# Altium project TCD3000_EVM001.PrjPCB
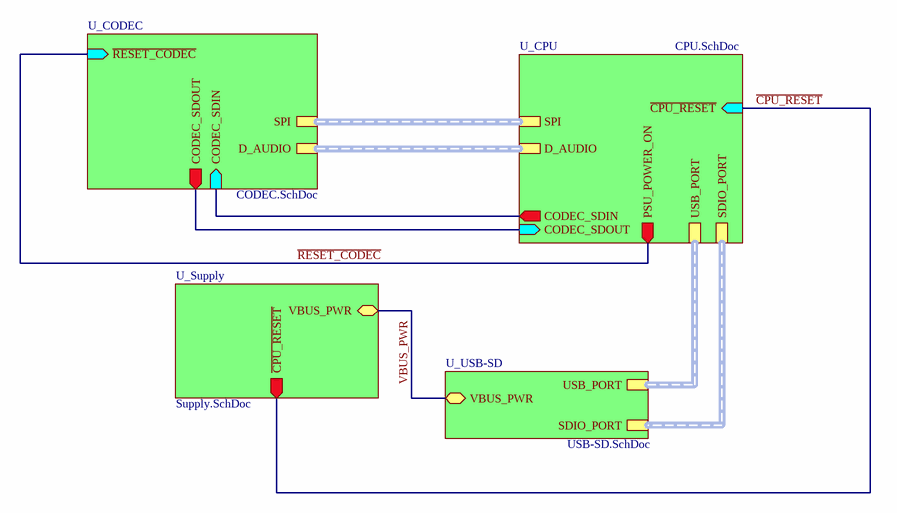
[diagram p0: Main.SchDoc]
6 sheets, 201 parts. Net scope: hierarchical (ports join the sheet entries above them; power ports are global).
Sheets:
  Main.SchDoc
    U_CPU = CPU.SchDoc
      U_CPU_Supply = CPU_Supply.SchDoc
    U_USB-SD = USB-SD.SchDoc
    U_CODEC = CODEC.SchDoc
    U_Supply = Supply.SchDoc

## Sheet Main.SchDoc: TCD3000-EVM001 REV2.0
size A4; Organization: TC Applied Technologies; Address4: address 4; DocumentNumber: 1; Revision: F; SheetNumber: 1; SheetTotal: 6

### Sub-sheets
U_CODEC = CODEC.SchDoc: SPI (harness SPI), D_AUDIO (harness D_AUDIO), CODEC_SDIN (in), CODEC_SDOUT (out), ~{RESET_CODEC} (in)
U_CPU = CPU.SchDoc: SDIO_PORT (harness SDIO), USB_PORT (harness USB), SPI (harness SPI), ~{CPU_RESET} (in), D_AUDIO (harness D_AUDIO), CODEC_SDIN (out), CODEC_SDOUT (in), PSU_POWER_ON (out)
U_Supply = Supply.SchDoc: ~{CPU_RESET} (out), VBUS_PWR
U_USB-SD = USB-SD.SchDoc: USB_PORT (harness USB), SDIO_PORT (harness SDIO), VBUS_PWR

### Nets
~{CPU_RESET}: sheet U_CPU/~{CPU_RESET}, sheet U_Supply/~{CPU_RESET}
CODEC_SDIN: sheet U_CPU/CODEC_SDIN, sheet U_CODEC/CODEC_SDIN
CODEC_SDOUT: sheet U_CPU/CODEC_SDOUT, sheet U_CODEC/CODEC_SDOUT
~{RESET_CODEC}: sheet U_CPU/PSU_POWER_ON, sheet U_CODEC/~{RESET_CODEC}  [project net PSU_POWER_ON]
VBUS_PWR: sheet U_USB-SD/VBUS_PWR, sheet U_Supply/VBUS_PWR

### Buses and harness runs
harness sheet U_CODEC/D_AUDIO = sheet U_CPU/D_AUDIO
harness sheet U_CODEC/SPI = sheet U_CPU/SPI
harness sheet U_CPU/SDIO_PORT = sheet U_USB-SD/SDIO_PORT
harness sheet U_CPU/USB_PORT = sheet U_USB-SD/USB_PORT

## Sheet CPU.SchDoc: TCD3000-EVM001 REV2.0
size A3; Organization: TC Applied Technologies; DocumentNumber: 1; Revision: F; SheetNumber: 4; SheetTotal: 6
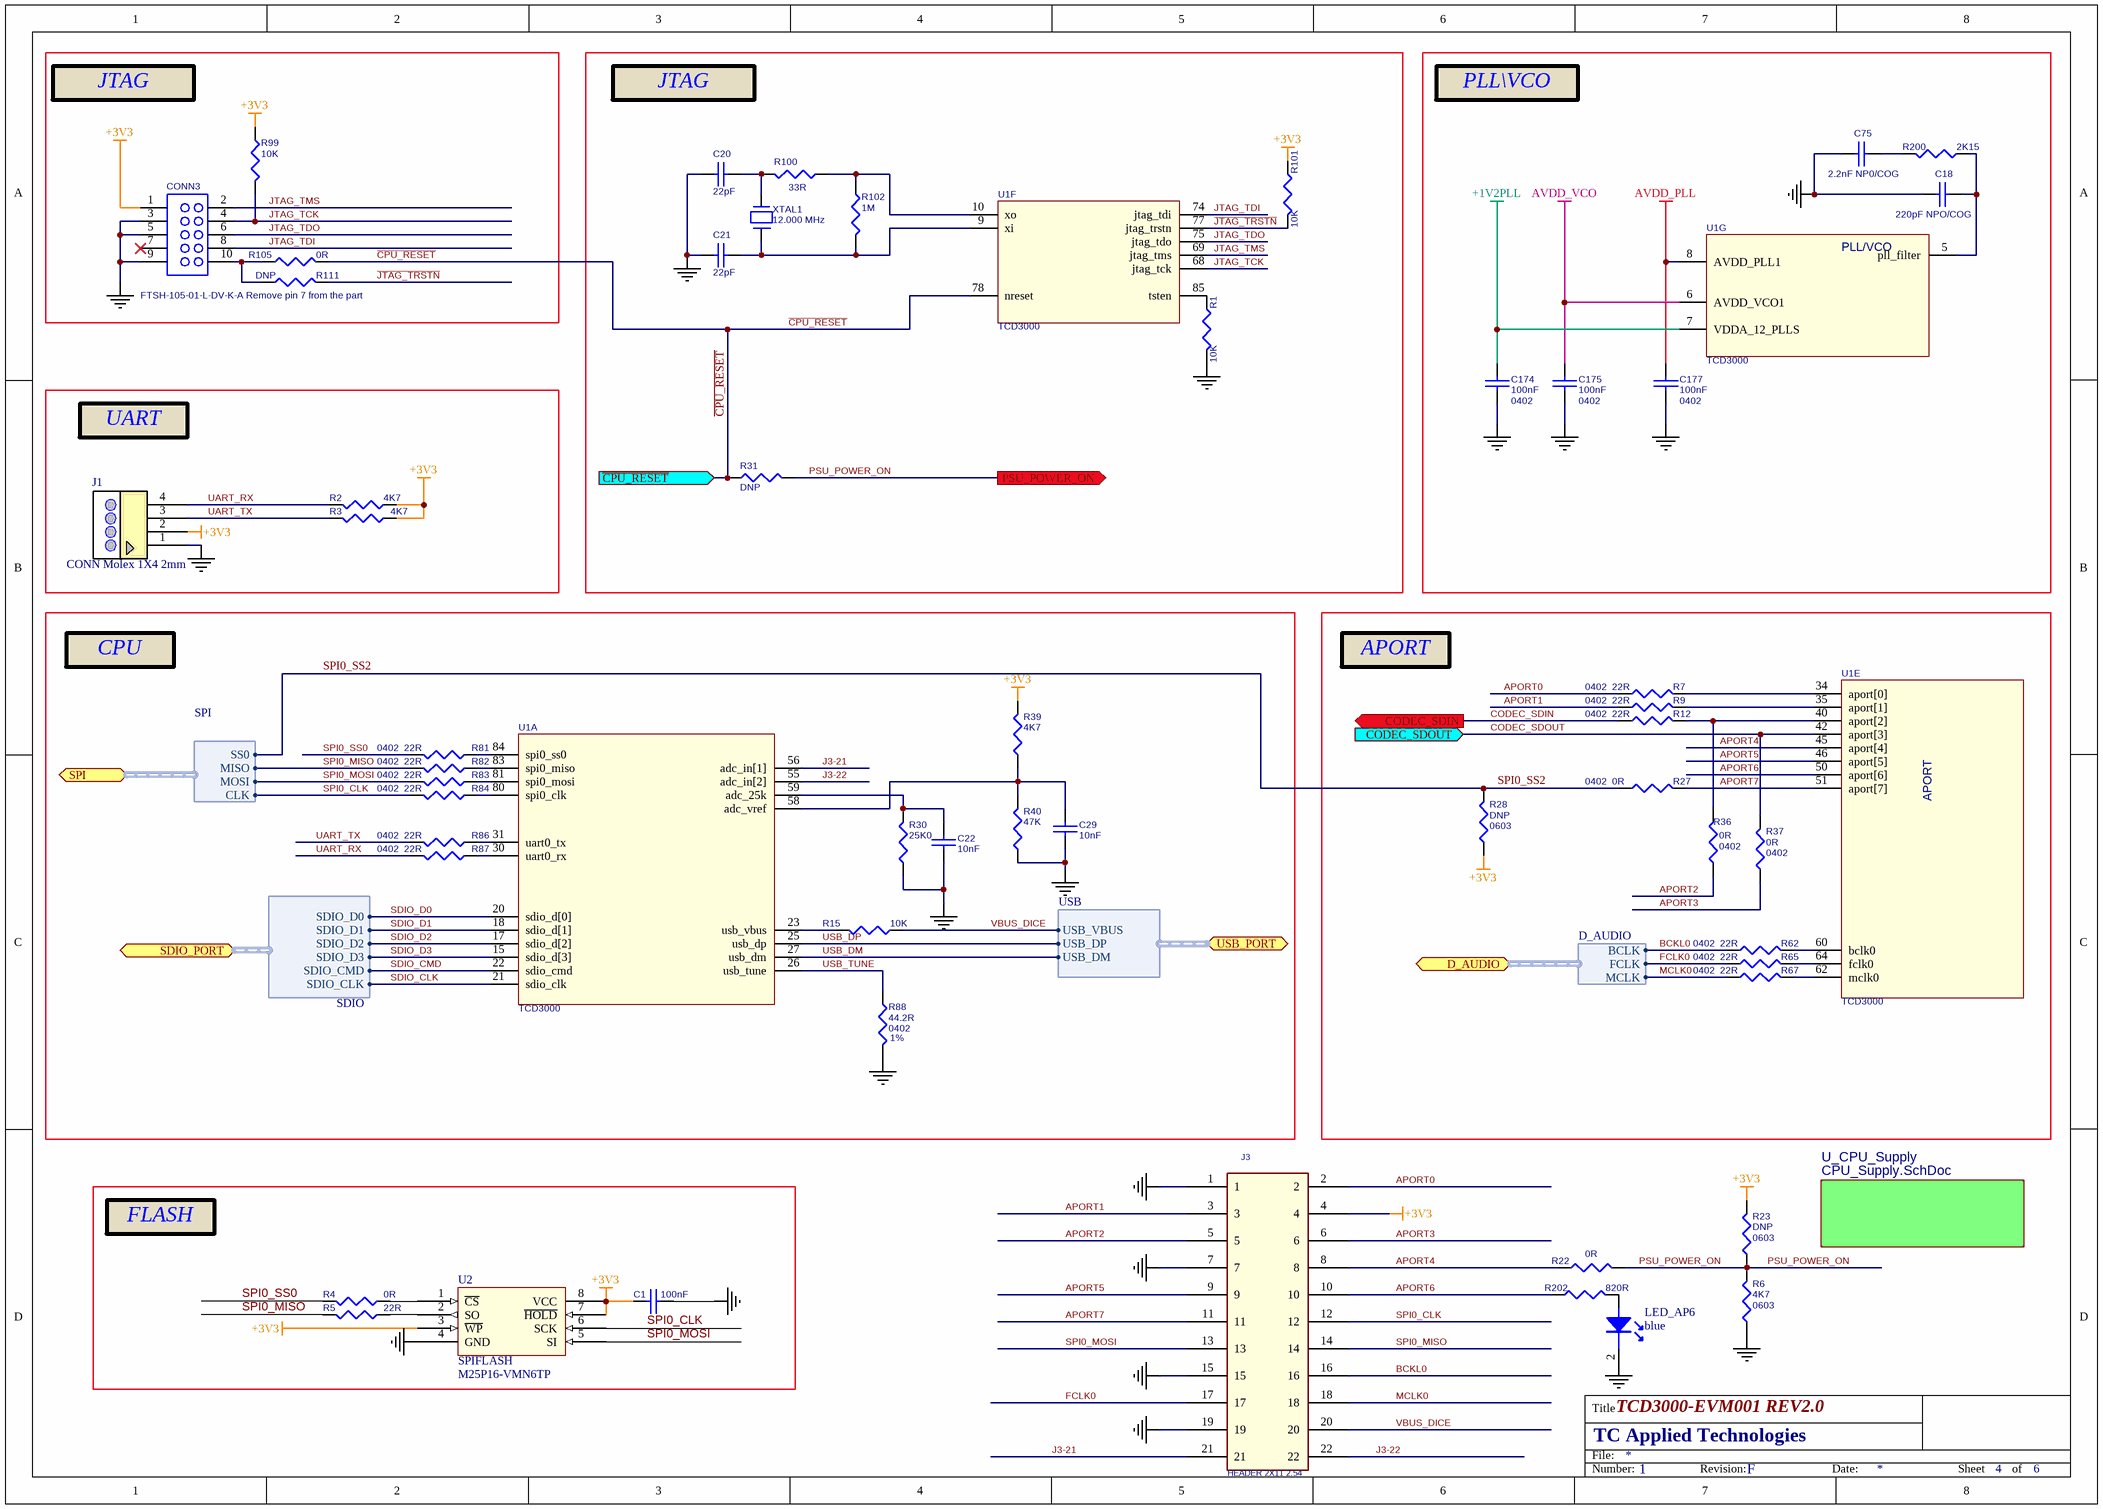
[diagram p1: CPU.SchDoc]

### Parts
C1  100nF  [0402_C]
C18  220pF NPO/COG  [0603_c]
C20  22pF  [0603_c]
C21  22pF  [0603_c]
C22  10nF  [0402_C]
C29  10nF  [0402_C]
C75  2.2nF NP0/COG  [0603_c]
C174  100nF  CASE: 0402  [0402_C]
C175  100nF  CASE: 0402  [0402_C]
C177  100nF  CASE: 0402  [0402_C]
CONN3  FTSH-105-01-L-DV-K-A Remove pin 7 from the part  [FTSH-105-01-L-DV-K-A]
J1  CONN Molex 1X4 2mm  [MOLEX 4POS 2MM VERT]
J3  HEADER 2X11 2.54  [CON/2X11/.100]
LED_AP6  blue  [LED_1 0805]
R1  10K  [0603_R]
R2  4K7  [0603_R]
R3  4K7  [0603_R]
R4  0R  [0402_R]
R5  22R  [0603_R]
R6  4K7  CASE: 0603  [0603_R]
R7  22R  CASE: 0402  [0402_R]
R9  22R  CASE: 0402  [0402_R]
R12  22R  CASE: 0402  [0402_R]
R15  10K  [0603_R]
R22  0R  [0402_R]
R23  DNP  CASE: 0603  [0603_R]
R27  0R  CASE: 0402  [0402_R]
R28  DNP  CASE: 0603  [0603_R]
R30  25K0  [0603_R]
R31  DNP  [0603_R]
R36  0R  CASE: 0402  [0402_R]
R37  0R  CASE: 0402  [0402_R]
R39  4K7  [0402_R]
R40  47K  [0402_R]
R62  22R  CASE: 0402  [0402_R]
R65  22R  CASE: 0402  [0402_R]
R67  22R  CASE: 0402  [0402_R]
R81  22R  CASE: 0402  [0402_R]
R82  22R  CASE: 0402  [0402_R]
R83  22R  CASE: 0402  [0402_R]
R84  22R  CASE: 0402  [0402_R]
R86  22R  CASE: 0402  [0402_R]
R87  22R  CASE: 0402  [0402_R]
R88  44.2R  CASE: 0402  TOLL: 1%  [0402_R]
R99  10K  [0603_R]
R100  33R  [0603_R]
R101  10K  [0603_R]
R102  1M  [0603_R]
R105  0R  [0402_R]
R111  DNP  [0603_R]
R200  2K15  [0603_R]
R202  820R  [0603_R]
U1  TCD3000  [QFN40P1000X1000X90-88USR]  (parts A,E,F,G of 7)
U2  SPIFLASH  Manufacturer Code: M25P16-VMN6TP  [SOIC150-8N]
XTAL1  12.000 MHz  [TXC 7A SERIES]

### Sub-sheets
U_CPU_Supply = CPU_Supply.SchDoc: no entries

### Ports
CODEC_SDIN (out), CODEC_SDOUT (in), D_AUDIO (harness D_AUDIO), PSU_POWER_ON (out), SDIO_PORT (harness SDIO), SPI (harness SPI), USB_PORT (harness USB), ~{CPU_RESET} (in)

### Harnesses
SDIO: SDIO_D1, SDIO_D2, SDIO_D3, SDIO_CMD, SDIO_CLK, SDIO_D0
USB: USB_VBUS, USB_DP, USB_DM
SPI: CLK, MISO, MOSI, SS0
D_AUDIO: BCLK, FCLK, MCLK

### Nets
+1V2PLL: C174.1 U1.7(VDDA_12_PLLS)
+3V3: C1.1 CONN3.1 J1.2 J3.4 R2.1 R3.1 R23.1 R28.2 R39.2 R99.2 R101.2 U2.3(~{WP}) U2.7(~{HOLD}) U2.8(VCC)
AVDD_PLL: C177.1 U1.8(AVDD_PLL1)
AVDD_VCO: C175.1 U1.6(AVDD_VCO1)
DGND: C1.2 C18.1 C20.2 C21.2 C22.1 C29.1 C75.1 C174.2 C175.2 C177.2 CONN3.3 CONN3.5 CONN3.9 J1.1 J3.1 J3.7 J3.15 J3.19 LED_AP6.2 R1.1 R6.2 R30.1 R40.1 R88.2 U2.4(GND)
APORT0: J3.2 R7.2
APORT1: J3.3 R9.2
APORT2: J3.5 R36.2
APORT3: J3.6 R37.2
APORT4: J3.8 R22.1 U1.45(aport[4])
APORT5: J3.9 U1.46(aport[5])
APORT6: J3.10 R202.1 U1.50(aport[6])
APORT7: J3.11 R27.1 U1.51(aport[7])
BCKL0: J3.16 R62.2 ; port D_AUDIO.BCLK
~{CPU_RESET}: R31.2 R105.1 U1.78(nreset) ; port ~{CPU_RESET}
CODEC_SDIN: R12.2 ; port CODEC_SDIN
CODEC_SDOUT: R37.1 U1.42(aport[3]) ; port CODEC_SDOUT
FCLK0: J3.17 R65.2 ; port D_AUDIO.FCLK
J3-21: J3.21 U1.56(adc_in[1])
J3-22: J3.22 U1.55(adc_in[2])
~{JTAG_TRSTN}: R101.1 R111.1 U1.77(jtag_trstn)
JTAG_TCK: CONN3.4 R99.1 U1.68(jtag_tck)
JTAG_TDI: CONN3.8 U1.74(jtag_tdi)
JTAG_TDO: CONN3.6 U1.75(jtag_tdo)
JTAG_TMS: CONN3.2 U1.69(jtag_tms)
MCLK0: J3.18 R67.2 ; port D_AUDIO.MCLK  [project net MCLK]
PSU_POWER_ON: R6.1 R22.2 R23.2 R31.1 ; port PSU_POWER_ON
SDIO_CLK: U1.21(sdio_clk) ; port SDIO_PORT.SDIO_CLK
SDIO_CMD: U1.22(sdio_cmd) ; port SDIO_PORT.SDIO_CMD
SDIO_D0: U1.20(sdio_d[0]) ; port SDIO_PORT.SDIO_D0
SDIO_D1: U1.18(sdio_d[1]) ; port SDIO_PORT.SDIO_D1
SDIO_D2: U1.17(sdio_d[2]) ; port SDIO_PORT.SDIO_D2
SDIO_D3: U1.15(sdio_d[3]) ; port SDIO_PORT.SDIO_D3
SPI0_CLK: J3.12 R84.2 U2.6(SCK) ; port SPI.CLK
SPI0_MISO: J3.14 R5.2 R82.2 ; port SPI.MISO
SPI0_MOSI: J3.13 R83.2 U2.5(SI) ; port SPI.MOSI
SPI0_SS0: R4.2 R81.2
SPI0_SS2: R27.2 R28.1 ; port SPI.SS0
UART_RX: J1.4 R2.2 R87.2
UART_TX: J1.3 R3.2 R86.2
USB_DM: U1.27(usb_dm) ; port USB_PORT.USB_DM  [project net HS_USB_N]
USB_DP: U1.25(usb_dp) ; port USB_PORT.USB_DP  [project net HS_USB_P]
USB_TUNE: R88.1 U1.26(usb_tune)
VBUS_DICE: J3.20 R15.2 ; port USB_PORT.USB_VBUS
NetC18_2: C18.2 R200.2 U1.5(pll_filter)
NetC20_1: C20.1 R100.2 XTAL1.1
NetC21_1: C21.1 R102.2 U1.9(xi) XTAL1.2
NetC22_2: C22.2 R30.2 U1.59(adc_25k)
NetC29_2: C29.2 R39.1 R40.2 U1.58(adc_vref)
NetC75_2: C75.2 R200.1
NetCONN3_10: CONN3.10 R105.2 R111.2
NetLED_AP6_1: LED_AP6.1 R202.2
NetR1_2: R1.2 U1.85(tsten)
NetR4_1: R4.1 U2.1(~{CS})
NetR5_1: R5.1 U2.2(SO)
NetR7_1: R7.1 U1.34(aport[0])
NetR9_1: R9.1 U1.35(aport[1])
NetR12_1: R12.1 R36.1 U1.40(aport[2])
NetR15_1: R15.1 U1.23(usb_vbus)
NetR62_1: R62.1 U1.60(bclk0)
NetR65_1: R65.1 U1.64(fclk0)
NetR67_1: R67.1 U1.62(mclk0)
NetR81_1: R81.1 U1.84(spi0_ss0)
NetR82_1: R82.1 U1.83(spi0_miso)
NetR83_1: R83.1 U1.81(spi0_mosi)
NetR84_1: R84.1 U1.80(spi0_clk)
NetR86_1: R86.1 U1.31(uart0_tx)
NetR87_1: R87.1 U1.30(uart0_rx)
NetR100_1: R100.1 R102.1 U1.10(xo)

Not connected (* = marked no-connect by the designer): CONN3 7*

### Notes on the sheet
- JTAG
- PLL\VCO
- UART
- CPU
- APORT
- FLASH

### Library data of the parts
C1 C174 C175 C177 = C: Capacitor SMD Ceramic X7R; Manufacturer Code: C1005X7R1H104K050BB; VOLT: 50V; TOLL: X7R 10%
C18 = C: Capacitor SMD Ceramic NPO/COG; Manufacturer Code: C1608C0G1H221K080AA
C20 C21 = C: Capacitor SMD Ceramic X7R; Manufacturer Code: 06035C220JAT2A
C22 C29 = C: Capacitor SMD Ceramic X7R; Manufacturer Code: C1005X7R1H103K050BB; VOLT: 50V; TOLL: X7R 10%
C75 = C: Capacitor SMD Ceramic NP0/GOG; Manufacturer Code: C0603C222K5GAC7867
CONN3 = FTSH-105-01-L-DV-K-A: .050'' Micro Terminal Strip; Manufacturer: Samtec
J1 = CON Molex 1X4 90° 2.5mm: CONN HEADER 4POS 2MM VERT T/H; Manufacturer: Molex Inc; Manufacturer Code: Molex Inc 0894000420
J3 = HEADER 2X11 2.54: HEADER 2 X 11 2.54; Manufacturer Code: 1-826656-1
LED_AP6 = LED: Manufacturer Code: HSMN-C170
R1 R15 R99 R101 = R: Resistor SMD; Manufacturer Code: ERJ-3EKF1002V; TOLL: 1%
R2 R3 R6 = R: Resistor SMD; Manufacturer Code: ERJ-3EKF4701V; TOLL: 1%
R4 R22 R27 R36 R37 R105 = R: Resistor SMD; Manufacturer Code: ERJ-2GE0R00X; TOLL: 1%
R5 = R: Resistor SMD; Manufacturer Code: ERJ-3EKF22R0V; TOLL: 1%
R7 R9 R62 R65 R67 R81-R84 R86 R87 = R: Resistor SMD; Manufacturer Code: ERJ-2RKF22R0X; TOLL: 1%
R12 = R: Resistor SMD; Manufacturer Code: ERJ-2RKF22R0X; TOLL: 1%; VALUE: 0R
R23 = R: Resistor SMD; TOLL: 1%; VALUE: 68K
R28 R111 = R: Resistor SMD; TOLL: 1%; VALUE: NP
R30 = R: Resistor SMD; Manufacturer Code: ERJ-3EKF2502V; TOLL: 1%; VALUE: 25K
R31 = R: Resistor SMD; TOLL: 1%; VALUE: 0R
R39 = R: Resistor SMD; Manufacturer Code: ERJ-2RKF4701X; TOLL: 1%
R40 = R: Resistor SMD; Manufacturer Code: ERJ-2RKF4702X; TOLL: 1%
R88 = R: Resistor SMD; Manufacturer Code: ERJ-2RKF44R2X
R100 = R: Resistor SMD; Manufacturer Code: MCR03ERTF33R0; TOLL: 1%
R102 = R: Resistor SMD; Manufacturer Code: ERJ-3EKF1004V; TOLL: 1%
R200 = R: Resistor SMD; Manufacturer Code: CRCW06032K15FKEA; TOLL: 1%
R202 = R: Resistor SMD; Manufacturer Code: ERJ-3EKF8200V; TOLL: 1%
U1 = TCD3000-SOCKET
U2 = SPIFLASH: IC FLASH 16MBIT 75MHZ 8SO; Manufacturer: Micron Technology Inc
XTAL1 = Crystal SMD: 12.000 MHz +/-30ppm 18pF; Manufacturer: TXC; Manufacturer Code: 7A-12.000MAAJ-T

## Sheet CPU_Supply.SchDoc: TCD3000-EVM001 REV2.0
size A4; Organization: TC Applied Technologies; Address4: address 4; DocumentNumber: 1; Revision: F; SheetNumber: 5; SheetTotal: 6
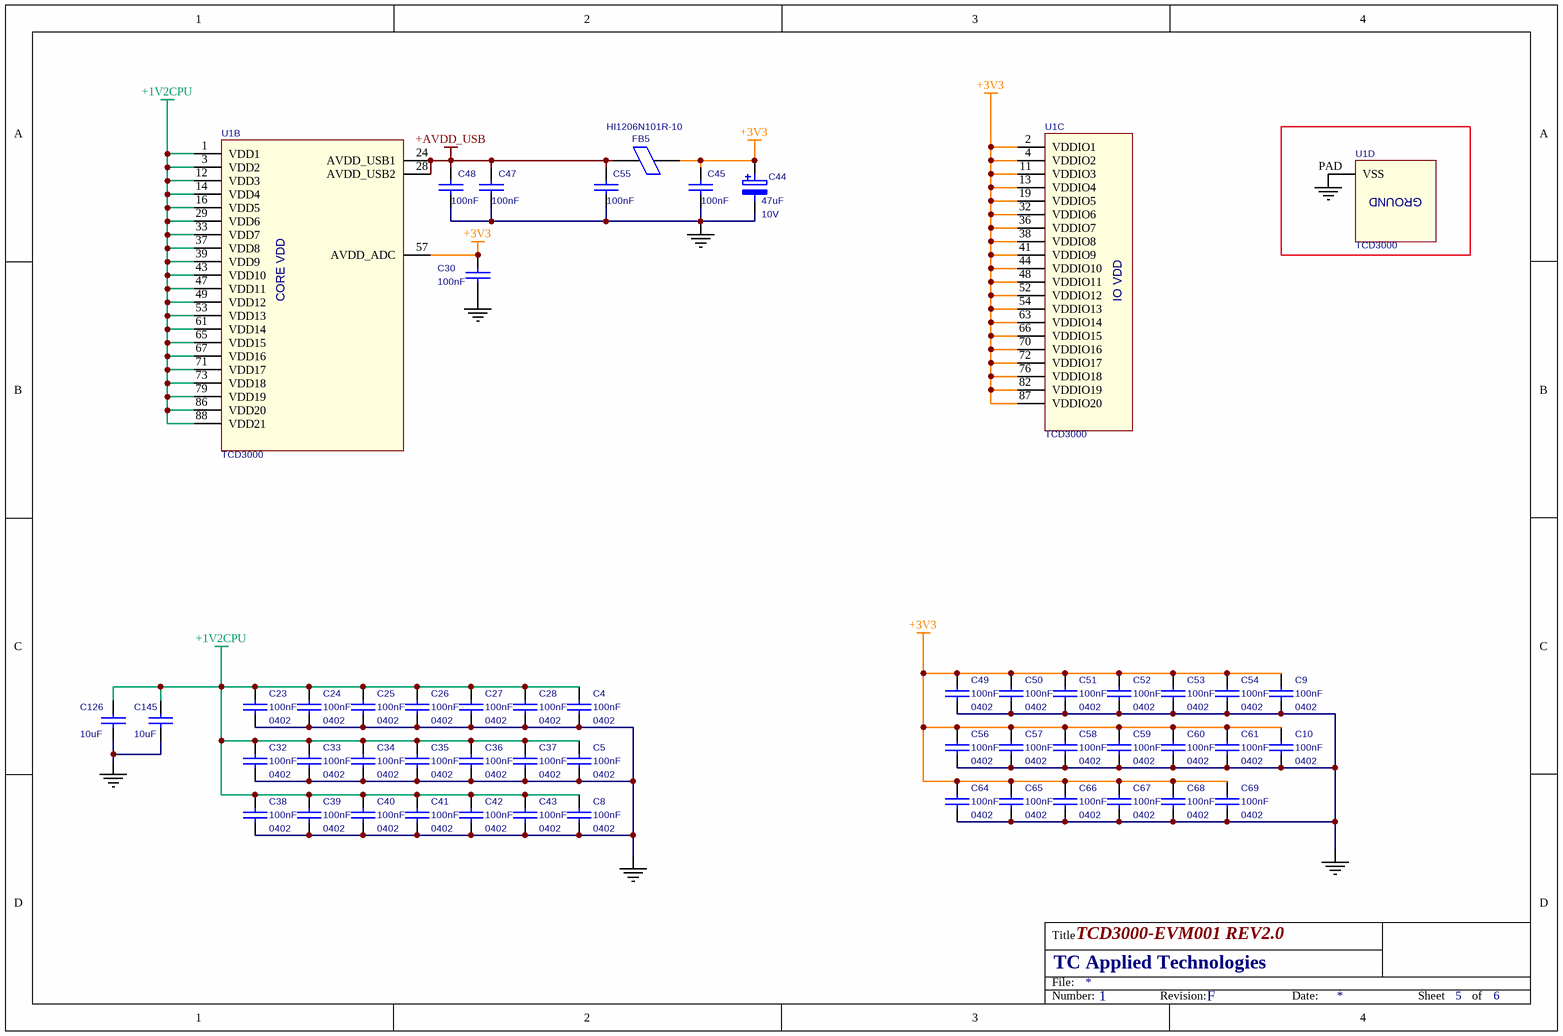
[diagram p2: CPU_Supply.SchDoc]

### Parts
C4  100nF  CASE: 0402  [0402_C]
C5  100nF  CASE: 0402  [0402_C]
C8  100nF  CASE: 0402  [0402_C]
C9  100nF  CASE: 0402  [0402_C]
C10  100nF  CASE: 0402  [0402_C]
C23  100nF  CASE: 0402  [0402_C]
C24  100nF  CASE: 0402  [0402_C]
C25  100nF  CASE: 0402  [0402_C]
C26  100nF  CASE: 0402  [0402_C]
C27  100nF  CASE: 0402  [0402_C]
C28  100nF  CASE: 0402  [0402_C]
C30  100nF  [0402_C]
C32  100nF  CASE: 0402  [0402_C]
C33  100nF  CASE: 0402  [0402_C]
C34  100nF  CASE: 0402  [0402_C]
C35  100nF  CASE: 0402  [0402_C]
C36  100nF  CASE: 0402  [0402_C]
C37  100nF  CASE: 0402  [0402_C]
C38  100nF  CASE: 0402  [0402_C]
C39  100nF  CASE: 0402  [0402_C]
C40  100nF  CASE: 0402  [0402_C]
C41  100nF  CASE: 0402  [0402_C]
C42  100nF  CASE: 0402  [0402_C]
C43  100nF  CASE: 0402  [0402_C]
C44  47uF  VOLT: 10V  [C TANT CASE B]
C45  100nF  [0402_C]
C47  100nF  [0402_C]
C48  100nF  [0402_C]
C49  100nF  CASE: 0402  [0402_C]
C50  100nF  CASE: 0402  [0402_C]
C51  100nF  CASE: 0402  [0402_C]
C52  100nF  CASE: 0402  [0402_C]
C53  100nF  CASE: 0402  [0402_C]
C54  100nF  CASE: 0402  [0402_C]
C55  100nF  [0402_C]
C56  100nF  CASE: 0402  [0402_C]
C57  100nF  CASE: 0402  [0402_C]
C58  100nF  CASE: 0402  [0402_C]
C59  100nF  CASE: 0402  [0402_C]
C60  100nF  CASE: 0402  [0402_C]
C61  100nF  CASE: 0402  [0402_C]
C64  100nF  CASE: 0402  [0402_C]
C65  100nF  CASE: 0402  [0402_C]
C66  100nF  CASE: 0402  [0402_C]
C67  100nF  CASE: 0402  [0402_C]
C68  100nF  CASE: 0402  [0402_C]
C69  100nF  CASE: 0402  [0402_C]
C126  10uF  [0805_C]
C145  10uF  [0805_C]
FB5  HI1206N101R-10  [1206_l]
U1  TCD3000  [TCD-3000 SOCKET]  (parts B,C,D of 7)

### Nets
+1V2CPU: C4.2 C5.2 C8.2 C23.2 C24.2 C25.2 C26.2 C27.2 C28.2 C32.2 C33.2 C34.2 C35.2 C36.2 C37.2 C38.2 C39.2 C40.2 C41.2 C42.2 C43.2 C126.2 C145.2 U1.1(VDD1) U1.3(VDD2) U1.12(VDD3) U1.14(VDD4) U1.16(VDD5) U1.29(VDD6) U1.33(VDD7) U1.37(VDD8) U1.39(VDD9) U1.43(VDD10) U1.47(VDD11) U1.49(VDD12) U1.53(VDD13) U1.61(VDD14) U1.65(VDD15) U1.67(VDD16) U1.71(VDD17) U1.73(VDD18) U1.79(VDD19) U1.86(VDD20) U1.88(VDD21)
+3V3: C9.2 C10.2 C30.2 C44.1+ C45.2 C49.2 C50.2 C51.2 C52.2 C53.2 C54.2 C56.2 C57.2 C58.2 C59.2 C60.2 C61.2 C64.2 C65.2 C66.2 C67.2 C68.2 C69.2 FB5.2 U1.2(VDDIO1) U1.4(VDDIO2) U1.11(VDDIO3) U1.13(VDDIO4) U1.19(VDDIO5) U1.32(VDDIO6) U1.36(VDDIO7) U1.38(VDDIO8) U1.41(VDDIO9) U1.44(VDDIO10) U1.48(VDDIO11) U1.52(VDDIO12) U1.54(VDDIO13) U1.57(AVDD_ADC) U1.63(VDDIO14) U1.66(VDDIO15) U1.70(VDDIO16) U1.72(VDDIO17) U1.76(VDDIO18) U1.82(VDDIO19) U1.87(VDDIO20)
+AVDD_USB: C47.2 C48.2 C55.2 FB5.1 U1.24(AVDD_USB1) U1.28(AVDD_USB2)
DGND: C4.1 C5.1 C8.1 C9.1 C10.1 C23.1 C24.1 C25.1 C26.1 C27.1 C28.1 C30.1 C32.1 C33.1 C34.1 C35.1 C36.1 C37.1 C38.1 C39.1 C40.1 C41.1 C42.1 C43.1 C44.2 C45.1 C47.1 C48.1 C49.1 C50.1 C51.1 C52.1 C53.1 C54.1 C55.1 C56.1 C57.1 C58.1 C59.1 C60.1 C61.1 C64.1 C65.1 C66.1 C67.1 C68.1 C69.1 C126.1 C145.1 U1.PAD(VSS)

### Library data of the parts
C4 C5 C8-C10 C23-C28 C30 C32-C43 C45 C47-C61 C64-C69 = C: as C1 on sheet CPU
C44 = POL C: Pol Capacitor SMD Tantalum; Manufacturer Code: TAJB476K010RNJ; TOLL: 10%
C126 C145 = C: Capacitor SMD Ceramic X7R; Manufacturer Code: CL21B106KOQNNNE; VOLT: 16V; TOLL: 10%
FB5 = FERRITE BEAD: Ferrite Bead 3A 100Ohm; Manufacturer: Laird-Signal Integrity Products
U1 = TCD3000-SOCKET

## Sheet USB-SD.SchDoc: TCD3000-EVM001 REV2.0
size A4; Organization: TC Applied Technologies; Address4: address 4; DocumentNumber: 1; Revision: F; SheetNumber: 6; SheetTotal: 6
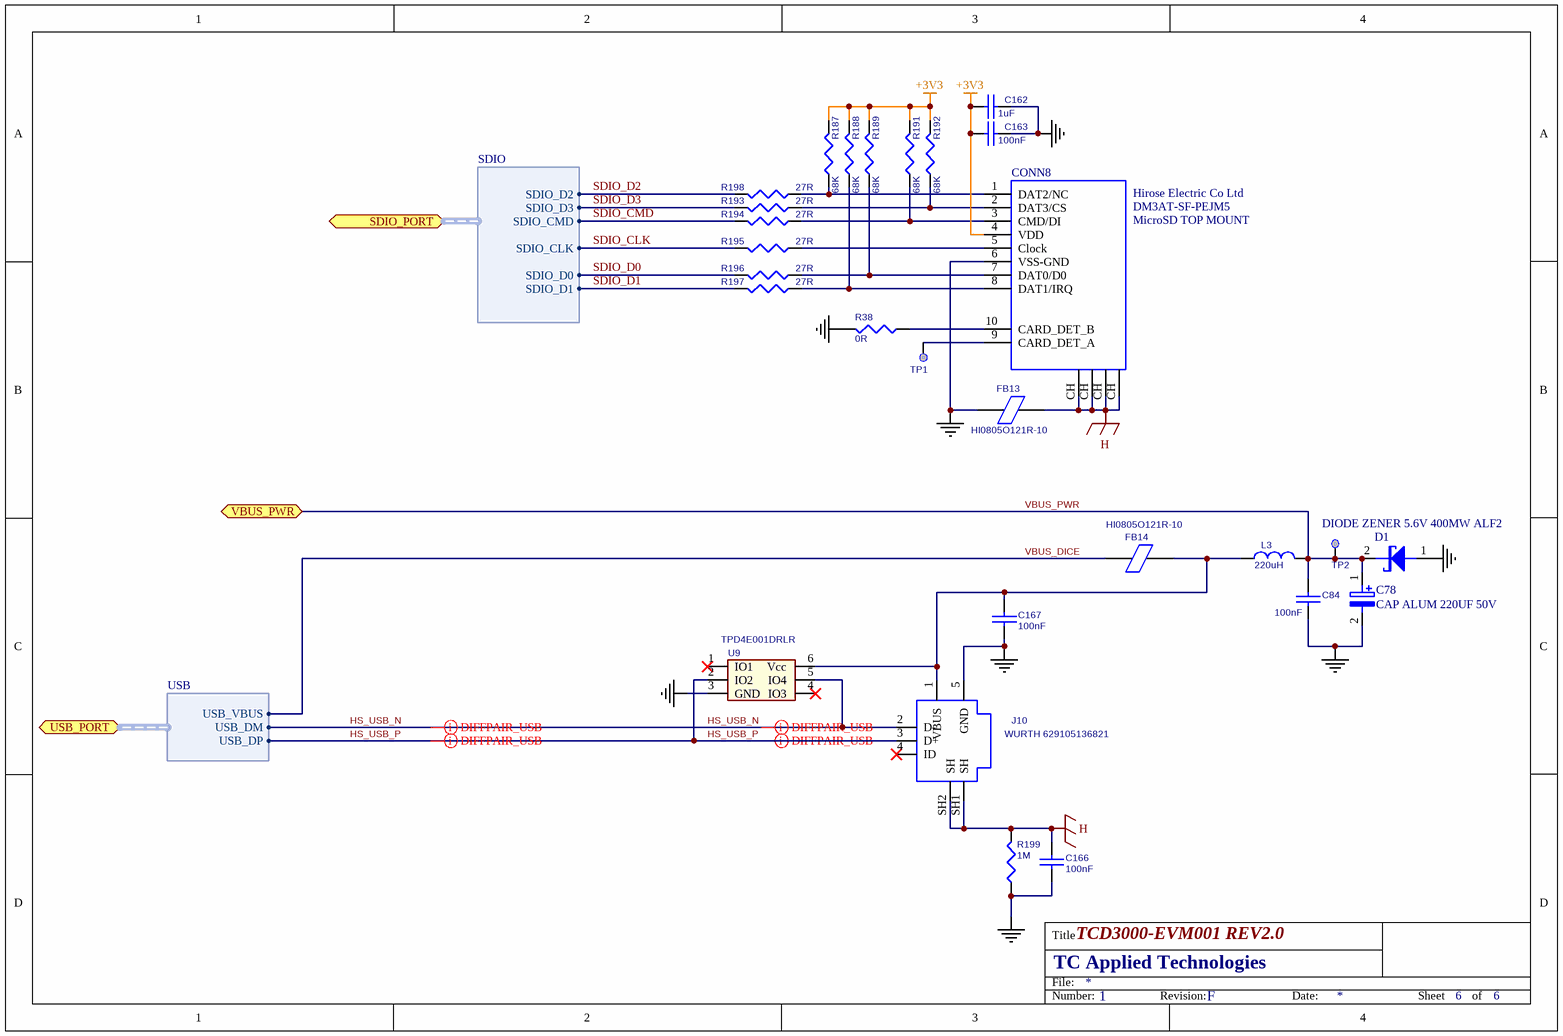
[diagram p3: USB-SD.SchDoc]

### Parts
C78  CAP ALUM 220UF 50V  [ALU_SMD_G]
C84  100nF  [0402_C]
C162  1uF  [0603_c]
C163  100nF  [0402_C]
C166  100nF  [0402_C]
C167  100nF  [0402_C]
CONN8  MicroSD TOP MOUNT  Manufacturer: Hirose Electric Co Ltd  Manufacturer Code: DM3AT-SF-PEJM5  [DM3AT]
D1  DIODE ZENER 5.6V 400MW ALF2  [DO-35]
FB13  HI0805O121R-10  [0805_L]
FB14  HI0805O121R-10  [0805_L]
J10  WURTH 629105136821  [Wurth - 629105136821]
L3  220uH  [TBD]
R38  0R  [0603_R]
R187  68K  [0603_R]
R188  68K  [0603_R]
R189  68K  [0603_R]
R191  68K  [0603_R]
R192  68K  [0603_R]
R193  27R  [0603_R]
R194  27R  [0603_R]
R195  27R  [0603_R]
R196  27R  [0603_R]
R197  27R  [0603_R]
R198  27R  [0603_R]
R199  1M  [0603_R]
TP1  TP  [Test Point 0.8 PTH]  (value not drawn)  (no BOM)
TP2  TP  [Test Point 0.8 PTH]  (value not drawn)  (no BOM)
U9  TPD4E001DRLR  [SOT6 (DRL)]

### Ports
SDIO_PORT (harness SDIO), USB_PORT (harness USB), VBUS_PWR

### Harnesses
USB: USB_VBUS, USB_DP, USB_DM
SDIO: SDIO_D1, SDIO_D2, SDIO_D3, SDIO_CMD, SDIO_CLK, SDIO_D0

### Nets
+3V3: C162.1 C163.1 CONN8.4(VDD) R187.2 R188.2 R189.2 R191.2 R192.2
DGND: C78.2 C84.2 C162.2 C163.2 C166.1 C167.1 CONN8.6(VSS-GND) D1.1 FB13.2 J10.5(GND) R38.2 R199.1 U9.3(GND)
H: C166.2 CONN8.CH FB13.1 J10.SH1(SH) J10.SH2(SH) R199.2
HS_USB_N: J10.2(D-) U9.5(IO4) ; port USB_PORT.USB_DM
HS_USB_P: J10.3(D+) U9.2(IO2) ; port USB_PORT.USB_DP
SDIO_CLK: R195.2 ; port SDIO_PORT.SDIO_CLK
SDIO_CMD: R194.2 ; port SDIO_PORT.SDIO_CMD
SDIO_D0: R196.2 ; port SDIO_PORT.SDIO_D0
SDIO_D1: R197.2 ; port SDIO_PORT.SDIO_D1
SDIO_D2: R198.2 ; port SDIO_PORT.SDIO_D2
SDIO_D3: R193.2 ; port SDIO_PORT.SDIO_D3
VBUS_DICE: FB14.2 ; port USB_PORT.USB_VBUS
VBUS_PWR: C78.1 C84.1 D1.2 L3.1 TP2.1 ; port VBUS_PWR
NetC167_2: C167.2 FB14.1 J10.1(VBUS) L3.2 U9.6(Vcc)
NetCONN8_1: CONN8.1(DAT2/NC) R187.1 R198.1
NetCONN8_2: CONN8.2(DAT3/CS) R192.1 R193.1
NetCONN8_3: CONN8.3(CMD/DI) R191.1 R194.1
NetCONN8_5: CONN8.5(Clock) R195.1
NetCONN8_7: CONN8.7(DAT0/D0) R189.1 R196.1
NetCONN8_8: CONN8.8(DAT1/IRQ) R188.1 R197.1
NetCONN8_9: CONN8.9(CARD_DET_A) TP1.1
NetCONN8_10: CONN8.10(CARD_DET_B) R38.1

Not connected (* = marked no-connect by the designer): J10 4(ID)*; U9 1(IO1)* 4(IO3)*

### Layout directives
differential pair: HS_USB_N, HS_USB_P

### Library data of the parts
C78 = POL C_1: CAP ALUM 220UF 50V 20% SMD; Manufacturer: Panasonic Electronic Components; Manufacturer Code: EEE-HA1H221P
C84 C163 C166 C167 = C: as C1 on sheet CPU
C162 = C: Capacitor SMD Ceramic X7R; Manufacturer Code: UMK107AB7105KA-T
CONN8 = HIROSE-DM3AT: CONN MICRO SD R/A PUSH-PUSH SMD; VALUE: MicroSD Memory Card Connector
D1 = DIODE ZENER: Manufacturer: NXP Semiconductors; Manufacturer Code: BZX79-B5V6,113
FB13 FB14 = FERRITE BEAD: Ferrite Bead 3.5A 120Ohm; Manufacturer: Laird-Signal Integrity Products
J10 = WURTH 629105136821: micro_USB, 5 pins, SMD
L3 = L_CHIP: INDUCTOR POWER 220UH 0.65A SMD 565 mOhm; Manufacturer: Bourns Inc.; Manufacturer Code: SRU1038-221Y
R38 = R: Resistor SMD; Manufacturer Code: MCR03ERTJ000; TOLL: 1%
R187-R189 R191 R192 = R: Resistor SMD; Manufacturer Code: ERJ-3EKF6802V; TOLL: 1%
R193-R198 = R: Resistor SMD; Manufacturer Code: ERJ-3EKF27R0V; TOLL: 1%
R199 = R: as R102 on sheet CPU
TP1 TP2 = Test Point 0.8mm: Manufacturer Code: DNP
U9 = TPD4E001DRLR: Low-Capacitance 4-Channel +/-15-kV ESD Protection Array for High-Speed Data Interfaces (1.5pF)); Manufacturer: Texas Instruments

## Sheet CODEC.SchDoc: TCD3000-EVM001 REV2.0
size A4; Organization: TC Applied Technologies; Address4: address 4; DocumentNumber: 1; Revision: F; SheetNumber: 2; SheetTotal: 6
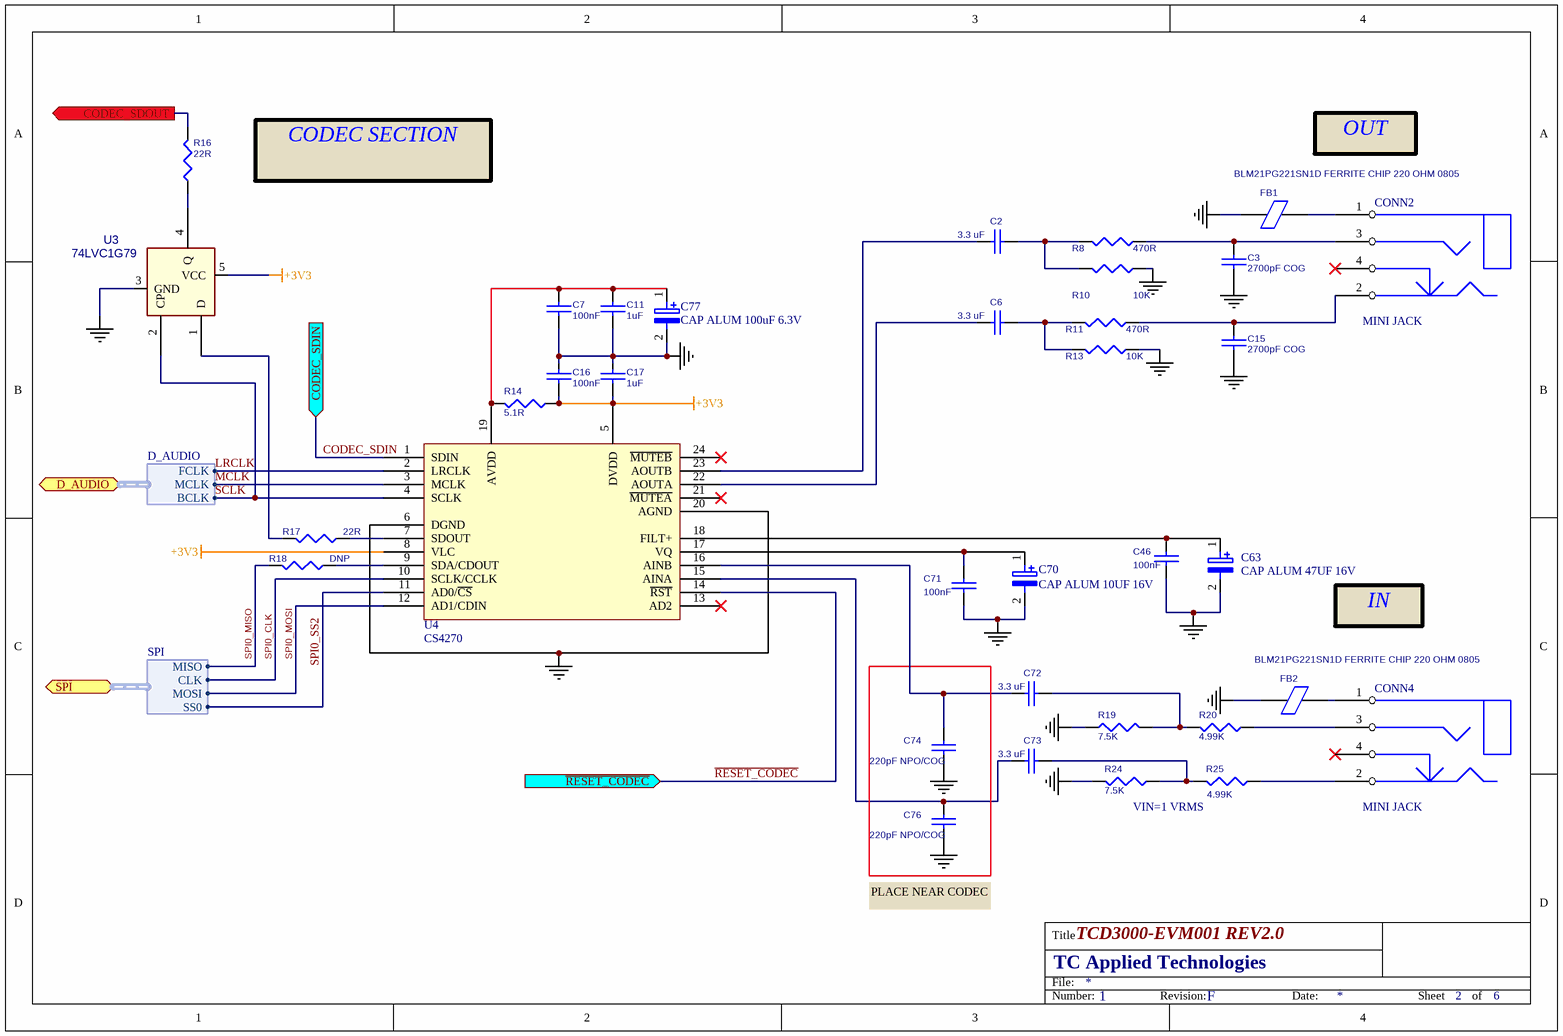
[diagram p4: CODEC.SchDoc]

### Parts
C2  3.3 uF  [1210_C]
C3  2700pF COG  [0603_c]
C6  3.3 uF  [1210_C]
C7  100nF  [0402_C]
C11  1uF  [0603_c]
C15  2700pF COG  [0603_c]
C16  100nF  [0402_C]
C17  1uF  [0603_c]
C46  100nF  [0402_C]
C63  CAP ALUM 47UF 16V  [ALU_SMD_D]
C70  CAP ALUM 10UF 16V  [ALU_SMD_B]
C71  100nF  [0402_C]
C72  3.3 uF  [1210_C]
C73  3.3 uF  [1210_C]
C74  220pF NPO/COG  [0603_c]
C76  220pF NPO/COG  [0603_c]
C77  CAP ALUM 100uF 6.3V  [ALU_SMD_C]
CONN2  MINI JACK  [SJ1_3514_SMT]
CONN4  MINI JACK  [SJ1_3514_SMT]
FB1  BLM21PG221SN1D FERRITE CHIP 220 OHM 0805  [0805_L]
FB2  BLM21PG221SN1D FERRITE CHIP 220 OHM 0805  [0805_L]
R8  470R  [0603_R]
R10  10K  [0603_R]
R11  470R  [0603_R]
R13  10K  [0603_R]
R14  5.1R  [0603_R]
R16  22R  [0402_R]
R17  22R  [0402_R]
R18  DNP  [0603_R]
R19  7.5K  [0603_R]
R20  4.99K  [0603_R]
R24  7.5K  [0603_R]
R25  4.99K  [0603_R]
U3  74LVC1G79  [SOT65P210X110-5N]
U4  CS4270  [TSOP65P640-24AN]

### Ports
CODEC_SDIN (in), CODEC_SDOUT (out), D_AUDIO (harness D_AUDIO), SPI (harness SPI), ~{RESET_CODEC} (in)

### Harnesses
SPI: CLK, MISO, MOSI, SS0
D_AUDIO: FCLK, BCLK, MCLK

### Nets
+3V3: C16.2 C17.2 R14.1 U3.5(VCC) U4.5(DVDD) U4.8(VLC)
DGND: C3.2 C7.2 C11.2 C15.2 C16.1 C17.1 C46.1 C63.2 C70.2 C71.1 C74.2 C76.2 C77.2 FB1.2 FB2.2 R10.1 R13.1 R19.1 R24.2 U3.3(GND) U4.6(DGND) U4.20(AGND)
CODEC_SDIN: U4.1(SDIN) ; port CODEC_SDIN
CODEC_SDOUT: R16.2 ; port CODEC_SDOUT
LRCLK: U4.2(LRCLK) ; port D_AUDIO.FCLK  [project net FCLK0]
MCLK: U4.3(MCLK) ; port D_AUDIO.MCLK
~{RESET_CODEC}: U4.14(~{RST}) ; port ~{RESET_CODEC}  [project net PSU_POWER_ON]
SCLK: U3.2(CP) U4.4(SCLK) ; port D_AUDIO.BCLK  [project net BCKL0]
SPI0_CLK: U4.10(SCLK/CCLK) ; port SPI.CLK
SPI0_MISO: R18.2 ; port SPI.MISO
SPI0_MOSI: U4.12(AD1/CDIN) ; port SPI.MOSI
SPI0_SS2: U4.11(AD0/~{CS}) ; port SPI.SS0
NetC2_1: C2.1 U4.23(AOUTB)
NetC2_2: C2.2 R8.2 R10.2
NetC3_1: C3.1 CONN2.3 R8.1
NetC6_1: C6.1 U4.22(AOUTA)
NetC6_2: C6.2 R11.2 R13.2
NetC7_1: C7.1 C11.1 C77.1 R14.2 U4.19(AVDD)
NetC15_1: C15.1 CONN2.2 R11.1
NetC46_2: C46.2 C63.1 U4.18(FILT+)
NetC70_1: C70.1 C71.2 U4.17(VQ)
NetC72_1: C72.1 C74.1 U4.16(AINB)
NetC72_2: C72.2 R19.2 R20.2
NetC73_1: C73.1 C76.1 U4.15(AINA)
NetC73_2: C73.2 R24.1 R25.2
NetCONN2_1: CONN2.1 FB1.1
NetCONN4_1: CONN4.1 FB2.1
NetCONN4_2: CONN4.2 R25.1
NetCONN4_3: CONN4.3 R20.1
NetR16_1: R16.1 U3.4(Q)
NetR17_1: R17.1 U4.7(SDOUT)
NetR17_2: R17.2 U3.1(D)
NetR18_1: R18.1 U4.9(SDA/CDOUT)

Not connected (* = marked no-connect by the designer): CONN2 4*; CONN4 4*; U4 13(AD2)* 21(~{MUTEA})* 24(~{MUTEB})*

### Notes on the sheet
- CODEC SECTION
- OUT
- IN
- VIN=1 VRMS
- PLACE NEAR CODEC

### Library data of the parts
C2 C6 C72 C73 = C: Capacitor SMD Ceramic X7R; Manufacturer: TDK Corporation; Manufacturer Code: CGA6P3X7R1H335K250AB; VOLT: 50V; TOLL: 10%; VALUE: CAP CER 3.3UF 50V 10% X7R 1210
C3 C15 = C: Capacitor SMD Ceramic X7R; Manufacturer Code: C0603C272K1RACTU
C7 C16 C46 C71 = C: as C1 on sheet CPU
C11 C17 = C: as C162 on sheet USB-SD
C63 = POL C_1: CAP ALUM 47UF 16V 20% SMD; Manufacturer: Nichicon; Manufacturer Code: UWT1C470MCL1GB
C70 = POL C_1: CAP ALUM 10UF 16V 20% SMD; Manufacturer: Panasonic Electronic Components; Manufacturer Code: EEE-1CA100SR
C74 C76 = C: as C18 on sheet CPU
C77 = POL C_1: CAP ALUM 100UF 6.3V 20% SMD; Manufacturer: Panasonic Electronic Components; Manufacturer Code: EEE-0JA101WR
CONN2 CONN4 = MINI JACK: Manufacturer: CUI Inc; Manufacturer Code: SJ1-3514-SMT-TR
FB1 FB2 = FERRITE BEAD: Ferrite Bead 3A 220Ohm; Manufacturer: Murata
R8 R11 = R: Resistor SMD; Manufacturer Code: ERJ-3EKF4700V; TOLL: 1%
R10 R13 = R: as R1 on sheet CPU
R14 = R: Resistor SMD; Manufacturer Code: RMCF0603FT5R10; TOLL: 1%
R16 = R: as R7 on sheet CPU
R17 = R: as R12 on sheet CPU
R18 = R: Resistor SMD; TOLL: 1%; VALUE: NP
R19 R24 = R: Resistor SMD; Manufacturer Code: ERJ-3EKF7501V; TOLL: 1%
R20 R25 = R: Resistor SMD; Manufacturer Code: ERJ-3EKF4991V; TOLL: 1%
U3 = 74LVC1G79: IC D-TYPE POS TRG SNGL 5TSSOP; Manufacturer: NXP; Manufacturer Code: 74VC1G79GW,125; VALUE: 74VC1G79
U4 = CS4270: CODEC; Manufacturer Code: CS4270-CZZ

## Sheet Supply.SchDoc: TCD3000-EVM001 REV2.0
size A4; Organization: TC Applied Technologies; Address4: address 4; DocumentNumber: 1; Revision: F; SheetNumber: 3; SheetTotal: 6
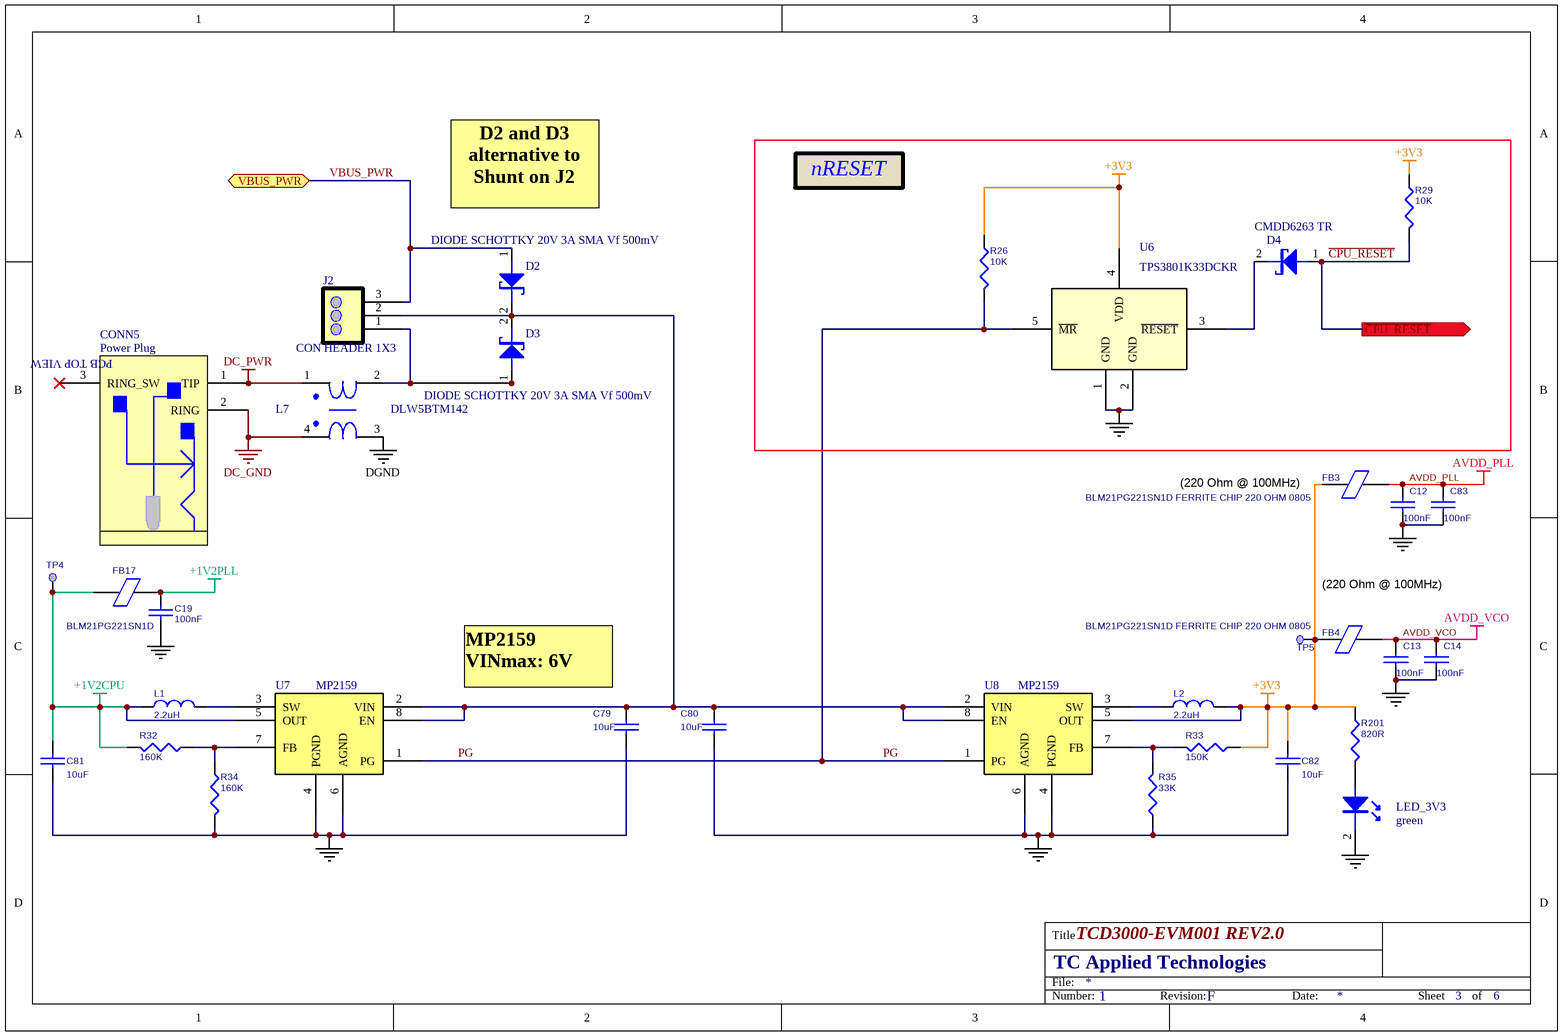
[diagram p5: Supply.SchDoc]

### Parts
C12  100nF  [0402_C]
C13  100nF  [0402_C]
C14  100nF  [0402_C]
C19  100nF  [0402_C]
C79  10uF  [0805_C]
C80  10uF  [0805_C]
C81  10uF  [0805_C]
C82  10uF  [0805_C]
C83  100nF  [0402_C]
CONN5  Power Plug  [CON_DC_GN000111]
D2  DIODE SCHOTTKY 20V 3A SMA Vf 500mV  [SMA]
D3  DIODE SCHOTTKY 20V 3A SMA Vf 500mV  [SMA]
D4  CMDD6263 TR  [SOD323]
FB3  BLM21PG221SN1D FERRITE CHIP 220 OHM 0805  [0805_L]
FB4  BLM21PG221SN1D FERRITE CHIP 220 OHM 0805  [0805_L]
FB17  BLM21PG221SN1D  [0805_L]
J2  CON HEADER 1X3  [HDR1X3]
L1  2.2uH  [1008]
L2  2.2uH  [1008]
L7  DLW5BTM142  [TBD]
LED_3V3  green  [LED_1 0805]
R26  10K  [0603_R]
R29  10K  [0603_R]
R32  160K  [0603_R]
R33  150K  [0603_R]
R34  160K  [0603_R]
R35  33K  [0603_R]
R201  820R  [0603_R]
TP4  TP  [Test Point 0.8 PTH]  (value not drawn)  (no BOM)
TP5  TP  [Test Point 0.8 PTH]  (value not drawn)  (no BOM)
U6  TPS3801K33DCKR  [SOT353-5N]
U7  MP2159  [TSOT23-8]
U8  MP2159  [TSOT23-8]

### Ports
VBUS_PWR, ~{CPU_RESET} (out)

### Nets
+1V2CPU: C81.2 FB17.2 L1.2 R32.1 TP4.1 U7.5(OUT)
+1V2PLL: C19.2 FB17.1
+3V3: C82.2 FB3.2 FB4.2 L2.2 R26.2 R29.2 R33.1 R201.1 TP5.1 U6.4(VDD) U8.5(OUT)
AVDD_PLL: C12.2 C83.2 FB3.1
AVDD_VCO: C13.2 C14.2 FB4.1
DC_GND: CONN5.2(RING) L7.4
DC_PWR: CONN5.1(TIP) L7.1
DGND: C12.1 C13.1 C14.1 C19.1 C79.1 C80.1 C81.1 C82.1 C83.1 L7.3 LED_3V3.2 R34.1 R35.1 U6.1(GND) U6.2(GND) U7.4(PGND) U7.6(AGND) U8.4(PGND) U8.6(AGND)
~{CPU_RESET}: D4.1 R29.1 ; port ~{CPU_RESET}
PG: R26.1 U6.5(~{MR}) U7.1(PG) U8.1(PG)
VBUS_PWR: D2.1 J2.3 ; port VBUS_PWR
NetC79_2: C79.2 C80.2 D2.2 D3.2 J2.2 U7.2(VIN) U7.8(EN) U8.2(VIN) U8.8(EN)
NetD3_1: D3.1 J2.1 L7.2
NetD4_2: D4.2 U6.3(~{RESET})
NetL1_1: L1.1 U7.3(SW)
NetL2_1: L2.1 U8.3(SW)
NetLED_3V3_1: LED_3V3.1 R201.2
NetR32_2: R32.2 R34.2 U7.7(FB)
NetR33_2: R33.2 R35.2 U8.7(FB)

Not connected (* = marked no-connect by the designer): CONN5 3(RING_SW)*

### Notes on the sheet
- D2 and D3
  alternative to
  Shunt on J2
- nRESET
- (220 Ohm @ 100MHz)
- (near C79) MP2159
  VINmax: 6V

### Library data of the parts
C12-C14 C19 C83 = C: as C1 on sheet CPU
C79-C82 = C: as C126 on sheet CPU_Supply
CONN5 = POWER_PLUG: POWER IN; Manufacturer: CUI; Manufacturer Code: PJ-102AH
D2 D3 = Diode Schottky: Do not assembly if shunt on J2 is present; Manufacturer: Micro Commercial Co; Manufacturer Code: SK32A-TP
D4 = Diode Schottky: DIODE SCHOTTKY 70V 15MA SOD323; Manufacturer: Central Semiconductor Corp
FB3 FB4 FB17 = FERRITE BEAD: as FB1 on sheet CODEC
J2 = CON HEADER 1X3: Header 1 x 3; Manufacturer: TE Connectivity; Manufacturer Code: 103321-3
L1 L2 = L_CHIP: Chip Inductor SMD, 2.2uH, 1.3A, 80mOhm; Manufacturer: Murata; Manufacturer Code: LQM2HPN2R2MG0L
L7 = DLW5BTN142: CHOKE COMMON MODE 1.4K OHM 2020; Manufacturer Code: DLW5BTM142TQ2L
LED_3V3 = LED: Manufacturer Code: HSMG-C170
R26 R29 = R: as R1 on sheet CPU
R32 R34 = R: Resistor SMD; Manufacturer Code: ERJ-3EKF1603V; TOLL: 1%
R33 = R: Resistor SMD; Manufacturer Code: MCR03ERTF1503; TOLL: 1%
R35 = R: Resistor SMD; Manufacturer Code: MCR03ERTF3302; TOLL: 1%
R201 = R: as R202 on sheet CPU
TP4 TP5 = Test Point 0.8mm: Manufacturer Code: DNP
U6 = TPS3801K33DCKR: Manufacturer: Texas Instruments
U7 U8 = MP2159: Voltage Regulators - Switching Regulators 1A, 6V, 1.5MHz COT Sync Step Dwn Swtchr; Manufacturer: MPS; Manufacturer Code: MP2159GJ-P

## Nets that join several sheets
+1V2CPU: CPU_Supply (44 pins), Supply (6 pins)
+1V2PLL: CPU (C174.1 U1.7), Supply (C19.2 FB17.1)
+3V3: CPU (14 pins), CPU_Supply (45 pins), USB-SD (8 pins), CODEC (6 pins), Supply (11 pins)
AVDD_PLL: CPU (C177.1 U1.8), Supply (C12.2 C83.2 FB3.1)
AVDD_VCO: CPU (C175.1 U1.6), Supply (C13.2 C14.2 FB4.1)
DGND: CPU (25 pins), CPU_Supply (50 pins), USB-SD (13 pins), CODEC (22 pins), Supply (19 pins)
BCKL0: CPU (J3.16 R62.2), CODEC (U3.2 U4.4)
~{CPU_RESET}: CPU (R31.2 R105.1 U1.78), Supply (D4.1 R29.1)
CODEC_SDIN: CPU (R12.2), CODEC (U4.1)
CODEC_SDOUT: CPU (R37.1 U1.42), CODEC (R16.2)
FCLK0: CPU (J3.17 R65.2), CODEC (U4.2)
HS_USB_N: CPU (U1.27), USB-SD (J10.2 U9.5)
HS_USB_P: CPU (U1.25), USB-SD (J10.3 U9.2)
MCLK: CPU (J3.18 R67.2), CODEC (U4.3)
PSU_POWER_ON: CPU (R6.1 R22.2 R23.2 R31.1), CODEC (U4.14)
SDIO_CLK: CPU (U1.21), USB-SD (R195.2)
SDIO_CMD: CPU (U1.22), USB-SD (R194.2)
SDIO_D0: CPU (U1.20), USB-SD (R196.2)
SDIO_D1: CPU (U1.18), USB-SD (R197.2)
SDIO_D2: CPU (U1.17), USB-SD (R198.2)
SDIO_D3: CPU (U1.15), USB-SD (R193.2)
SPI0_CLK: CPU (J3.12 R84.2 U2.6), CODEC (U4.10)
SPI0_MISO: CPU (J3.14 R5.2 R82.2), CODEC (R18.2)
SPI0_MOSI: CPU (J3.13 R83.2 U2.5), CODEC (U4.12)
SPI0_SS2: CPU (R27.2 R28.1), CODEC (U4.11)
VBUS_DICE: CPU (J3.20 R15.2), USB-SD (FB14.2)
VBUS_PWR: USB-SD (5 pins), Supply (D2.1 J2.3)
